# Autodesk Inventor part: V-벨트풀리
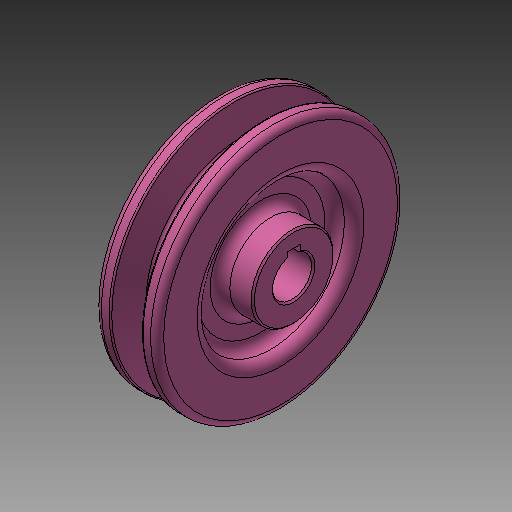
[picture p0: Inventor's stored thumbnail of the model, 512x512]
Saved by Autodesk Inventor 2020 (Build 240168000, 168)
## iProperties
Created: 2015-11
Part Number: V-벨트풀리
Material: 강철, 탄소
Document SubType Name: Modeling
Designer: mduedu
Density: 1 g/cm^3
Appearance: 분홍색
Author: mduedu
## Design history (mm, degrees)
sketch "스케치1"
  geometry: L1 (-9.5, 0)-(9.5, 0); L2 (0, 0)-(0, 37.7); L3 (-4.825, 37.7)-(-9.5, 37.7); L4 (-9.5, 37.7)-(-9.5, 0); L5 (0, 28.7)-(-2.074, 28.7); L6 (-2.074, 28.7)-(-4.825, 37.7); L7 (4.825, 37.7)-(9.5, 37.7); L8 (9.5, 37.7)-(9.5, 0); L9 (0, 28.7)-(2.074, 28.7); L10 (2.074, 28.7)-(4.825, 37.7); L11 (-9.5, 35)-(9.5, 35); 3 further points
  constraints: 22 end point, 7 point on line, 4 perpendicular, 3 symmetric about line, 1 coincident, 1 horizontal, 1 horizontal alignment, 1 midpoint, 1 vertical
  dimensions: "d0" = 19 distance of L1.start L1.end; "d2" = 75.4 diameter of L2.end L1 (derived); "d3" = 34 deg angle of L10 L6; "d4" = 6.3 distance between parallel lines of L11 L9; "d5" = 2.7 distance between parallel lines of L7 L11; "d6" = 8 distance of point (4, 35) point (-4, 35); "d7" = 70 diameter of L11 L1
revolve "회전1" sketch "스케치1" stored, may be unused: angle "d8" = 90 deg
sketch "스케치2"
  geometry: C1 r 22.5 at (0, 0); C2 r 12.5 at (0, 0); C3 r 37.7 at (0, 0) reference; 1 further point
  constraints: 2 centre point, 2 coincident
  dimensions: "d35" = 15.2 radial gap between concentric circles of C3 C1 (computed from d5); "d36" = 10 radial gap between concentric circles of C1 C2
extrude "돌출1" cut sketch "스케치2" distance "d11" = 6; taper "d12" = 0 deg
fillet "모깎기1" dims "d13" = 3
feature "면 이동1"
fillet "모깎기2" dims "d14" = 3
fillet "모깎기3" dims "d15" = 1, "d16" = 0.5, "d17" = 2
hole "구멍1" diameter "d20" = 12; stored, may be unused: countersink angle "d24" = 90 deg, drill point angle "d26" = 118 deg; dims "d21" = 6, "d22" = 4, "d23" = 2, "d25" = 8, "d37" = 10, "d38" = 10
sketch "스케치3"
  geometry: L1 (-2, 0)-(2, 0); L2 (2, 0)-(2, 7.8); L3 (2, 7.8)-(-2, 7.8); L4 (-2, 7.8)-(-2, 0); C1 r 12.5 at (0, 0) reference; 2 further points
  constraints: 8 end point, 2 coincident, 2 parallel, 1 horizontal, 1 midpoint, 1 perpendicular
  dimensions: "d27" = 4 distance of L2.end L3.end; "d29" = 7.8 distance of L3.end L1.start
extrude "돌출2" cut sketch "스케치3" extent not by distance; stored distance "d30" = 6; taper "d31" = 0 deg
chamfer "모따기1" distance "d32" = 0.5; stored, may be unused: second distance "d33" = 2, angle "d34" = 45 deg
node "솔리드1"
mirror "대칭1"
